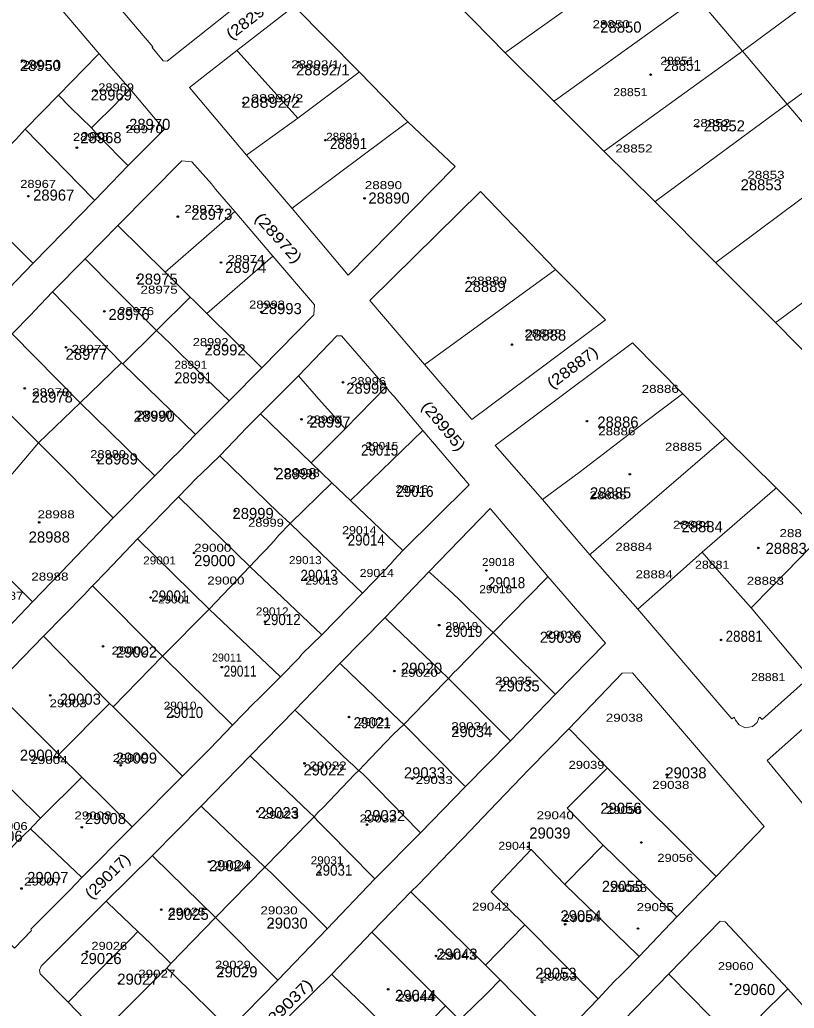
# Model space of a CAD drawing. Extents: x 650553 to 652508, y 239277 to 241647.
# Drawn here: x 650803.9 to 651055.5, y 240108.2 to 240429.4 of the extents above; entities that cross this region are included whole.
import ezdxf

# ---------------------------------------------------------------- set-up
doc = ezdxf.new("R2010")
doc.units = 0
doc.header["$PDMODE"] = 32
doc.header["$PDSIZE"] = 0.5
for name, color, linetype in [('19', 7, 'Continuous'), ('20', 7, 'Continuous'), ('6', 7, 'Continuous')]:
    doc.layers.add(name, color=color, linetype=linetype)
doc.layers.add('3', color=7, linetype='Continuous', lineweight=13)
doc.layers.add('5', color=7, linetype='Continuous', lineweight=13)

msp = doc.modelspace()

# ---------------------------------------------------------------- linework, layer by layer
at = {"layer": '3'}
for p, q in [((650859.02, 240407.32), (650874.38, 240419.42)), ((650953.54, 240373.57), (650977.886, 240348.17)), ((650956.67, 240270.53), (650975.44, 240248.44)), ((651002.97, 240217.17), (651045.69, 240167.24)), ((651000, 240104.22), (651014.69, 240119.32))]:
    msp.add_line(p, q, dxfattribs=at)
for points in [[(650832.82, 240437.45), (650847.119, 240420.59), (650846.839, 240420.337), (650850.433, 240416.034), (650851.723, 240415.899), (650884.79, 240442.24), (650880.06, 240447.42), (650879.76, 240447.15), (650863.92, 240463.81), (650845.72, 240482.71), (650830.23, 240498.54), (650814.88, 240515.1)], [(650963.52, 240488.81), (650925.94, 240459.4), (650925.48, 240455.02), (650945.81, 240434.62), (650961.6, 240418.64), (650977.42, 240402.86), (650993.66, 240386.64), (651010.27, 240370.23), (651029.97, 240350.43), (651049.39, 240330.95), (651070.65, 240309.46), (651091.16, 240289.1)], [(650779.71, 240413.95), (650806.93, 240441.68), (650809.94, 240441.52), (650829.64, 240418.33), (650839.71, 240406.79), (650850.75, 240393.72), (650839.03, 240381.99), (650828.2, 240370.72), (650808.21, 240350.23), (650794.9, 240336.56), (650781.8, 240323.07), (650768.64, 240309.58), (650755.41, 240295.93), (650741.91, 240281.85), (650728.35, 240268.09)], [(650874.38, 240419.42), (650893.01, 240433.8), (650914.15, 240412.42), (650929.978, 240396.24), (650945.306, 240381.724)], [(650945.306, 240381.724), (650910.543, 240346.406), (650892.33, 240368.07), (650877.5, 240385.33), (650859.02, 240407.32)], [(650787.85, 240313.79), (650794.22, 240320.09), (650795.45, 240321.44), (650801.38, 240327.33), (650807.43, 240333.47), (650808.64, 240334.74), (650814.48, 240340.93), (650825.07, 240351.63), (650835.69, 240362.55), (650856.48, 240383.5), (650859.73, 240383.17), (650866.12, 240376.02), (650867.47, 240374.36), (650873.78, 240367.01), (650886.12, 240352.53), (650899.62, 240336.77), (650899.4, 240333.52)], [(650935.379, 240317.358), (650917.632, 240338.107), (650953.54, 240373.57)], [(650977.886, 240348.17), (650994.115, 240331.864), (650950.714, 240299.452), (650935.379, 240317.358)], [(650899.4, 240333.52), (650882.46, 240316.3), (650871.84, 240305.54), (650860.95, 240294.62), (650855.64, 240289.08), (650853.1, 240286.62), (650847.74, 240281.16), (650834.26, 240267.54), (650817.4, 240250)], [(650831.89, 240250), (650842.09, 240260.74), (650848.02, 240266.82), (650849.46, 240268.28), (650855.46, 240274.36), (650861.39, 240280.47), (650862.83, 240281.82), (650868.89, 240287.72), (650875.8, 240294.96), (650877.19, 240296.42), (650882.1, 240301.29), (650894.43, 240313.67), (650906.83, 240326.67), (650908.39, 240326.62), (650921.14, 240311.96), (650922.6, 240310.52), (650922.89, 240310.12), (650923.87, 240308.73), (650925.52, 240306.94), (650934.86, 240295.88), (650949.85, 240278.27)], [(651002.88, 240324.42), (650958.28, 240291.03), (650973.65, 240273.43), (650989.05, 240255.53), (651004.69, 240237.82)], [(651087.57, 240239.54), (651064.69, 240262.07), (651049.64, 240277.24), (651033.12, 240293.56), (651019.23, 240307.86), (651002.88, 240324.42)], [(650949.85, 240278.27), (650928.34, 240256.94), (650925.35, 240253.81), (650924.47, 240252.7), (650921.88, 240250)], [(650810.87, 240121.85), (650831.93, 240142.92), (650846.95, 240157.77), (650862.81, 240173.82), (650878.68, 240190.23), (650893.26, 240205.07), (650907.87, 240220.21), (650922.56, 240235.11), (650936.76, 240250), (650956.67, 240270.53)], [(650725.8, 240250), (650717.68, 240241.5), (650704.33, 240227.66), (650704.28, 240225.38), (650711.26, 240218.39), (650712.71, 240217.11), (650719.74, 240210.07), (650727.37, 240202.26), (650728.66, 240201), (650749.48, 240180.42), (650768.67, 240200.35), (650774.4, 240206.01), (650775.68, 240207.3), (650781.35, 240212.99), (650786.73, 240218.51), (650788.1, 240219.97), (650794.65, 240226.67), (650800.78, 240232.68), (650801.8, 240233.71), (650808, 240240.22), (650817.4, 240250)], [(650831.89, 240250), (650827.51, 240245.39), (650826.78, 240244.72), (650824.86, 240242.62), (650811.56, 240229.04), (650794.97, 240212.04), (650781.7, 240198.63), (650756.76, 240173.01), (650770.74, 240159.15), (650772.14, 240157.81), (650772.9, 240157.17)], [(650820.08, 240146.53), (650824.01, 240150.65), (650840.42, 240167.09), (650856.74, 240183.6), (650864.2, 240191.06), (650865.62, 240192.52), (650872.93, 240200.2), (650879.96, 240207.28), (650881.3, 240208.63), (650888.53, 240215.85), (650894.49, 240221.96), (650895.64, 240223.36), (650902.04, 240229.48), (650915.18, 240243.03), (650921.88, 240250)], [(650975.44, 240248.44), (650994.17, 240226.84), (650977.88, 240210.19), (650963.32, 240195.05), (650948.63, 240180.21), (650934.05, 240165.2), (650919.2, 240150.25), (650903.76, 240134.01), (650887.65, 240117.31), (650871.97, 240101.3)], [(651004.69, 240237.82), (651035.18, 240202.17), (651035.94, 240202.81), (651036.11, 240202.584), (651036.41, 240201.81), (651037.555, 240200.241), (651039.578, 240199.34), (651041.891, 240199.7), (651043.384, 240201.007), (651044.011, 240202.539), (651044.251, 240202.72), (651045, 240202.01), (651060.45, 240215.71), (651087.57, 240239.54)], [(651046.67, 240188.64), (651067.79, 240207.42), (651095.04, 240231.27)], [(651002.97, 240217.17), (650999.6, 240217.03), (650982.26, 240199.01)], [(650982.26, 240199.01), (650969.26, 240185.78), (650956.52, 240172.47), (650947.93, 240163.4), (650943.47, 240158.84), (650933.41, 240148.36), (650930.92, 240145.99)], [(651068.91, 240161.72), (651055.65, 240177.73), (651046.67, 240188.64)], [(651045.69, 240167.24), (651030.09, 240151.02), (651017.38, 240137.84), (651005.05, 240125.03), (651000, 240119.78)], [(650818.42, 240144.86), (650819.503, 240145.95), (650820.08, 240146.53)], [(650930.92, 240145.99), (650924.769, 240139.63), (650918.26, 240132.9), (650905.2, 240119.22), (650892.49, 240106.64), (650880, 240093.44)], [(650785.53, 240144.32), (650788.76, 240141.22), (650788.44, 240140.92), (650802.1, 240127.68), (650807.72, 240133.44), (650807.48, 240133.9), (650818.42, 240144.86)], [(651014.69, 240119.32), (651031.37, 240136.47), (651033.06, 240136.27), (651053.41, 240114.49), (651063.76, 240102.95), (651079.09, 240086.95)], [(650810.87, 240121.85), (650810.26, 240120.51), (650810.53, 240119.41)], [(650871.97, 240101.3), (650850.3, 240079.24), (650829.93, 240099.47), (650819.64, 240110.18), (650810.53, 240119.41)], [(650991.82, 240111.21), (650996.99, 240116.84), (650999.05, 240118.78), (651000, 240119.78)], [(650978.95, 240097.99), (650985.03, 240104.18), (650986.07, 240105.29), (650991.82, 240111.21)]]:
    msp.add_lwpolyline(points, dxfattribs=at)
at = {"layer": '5'}
for p, q in [((651038.66, 240419.13), (651024.02, 240436.43)), ((651053.14, 240401.96), (651038.66, 240419.13)), ((650873.78, 240367.01), (650851.09, 240347.3)), ((650886.12, 240352.53), (650864.68, 240333.94)), ((651000, 240293.3), (651006.86, 240298.53)), ((650911.34, 240273.15), (650934.86, 240295.88)), ((651000, 240293.3), (650985.56, 240282.3)), ((650842.09, 240260.74), (650865.42, 240237.81)), ((651018.38, 240250), (651025.53, 240256.36)), ((651025.53, 240256.36), (651031.11, 240250)), ((650878.66, 240251.69), (650902.04, 240229.48)), ((650907.96, 240250), (650915.18, 240243.03)), ((651018.38, 240250), (651004.69, 240237.82)), ((651031.11, 240250), (651041.44, 240238.23)), ((650865.42, 240237.81), (650888.53, 240215.85)), ((650816.57, 240190.66), (650832.98, 240207.15)), ((650810.6, 240169.99), (650824.01, 240183.28)), ((650929.29, 240095.81), (650942.18, 240109.01))]:
    msp.add_line(p, q, dxfattribs=at)
for points in [[(650961.6, 240418.64), (650962.1, 240418.998), (651010.04, 240453.28)], [(651074.25, 240445.5), (651073.75, 240445.13), (651038.66, 240419.13)], [(650977.42, 240402.86), (650977.92, 240403.22), (651024.02, 240436.43)], [(651089.17, 240428.21), (651088.67, 240427.846), (651053.14, 240401.96)], [(650874.38, 240419.42), (650874.831, 240418.92), (650894.2, 240397.43)], [(650993.66, 240386.64), (650994.16, 240387.001), (651038.66, 240419.13)], [(650816.46, 240404.86), (650829.151, 240417.83), (650829.64, 240418.33)], [(650914.15, 240412.42), (650913.65, 240412.044), (650894.2, 240397.43)], [(650831.7, 240398.71), (650839.214, 240406.29), (650839.71, 240406.79)], [(650785.52, 240372.91), (650789.1, 240376.24), (650799.71, 240387.51), (650802.7, 240390.51), (650805.63, 240393.83), (650816.46, 240404.86)], [(650816.46, 240404.86), (650820.11, 240401.1), (650820.49, 240400.73), (650827.17, 240394.19), (650829.44, 240391.6), (650830.39, 240390.7)], [(651053.14, 240401.96), (651010.77, 240370.6), (651010.27, 240370.23)], [(651071.47, 240380.47), (651070.98, 240381.01), (651053.14, 240401.96)], [(650827.17, 240394.19), (650830.98, 240398.06), (650831.7, 240398.71)], [(650894.2, 240397.43), (650878, 240385.692), (650877.5, 240385.33)], [(650805.63, 240393.83), (650827.712, 240371.22), (650828.2, 240370.72)], [(650929.978, 240396.24), (650929.478, 240395.866), (650892.83, 240368.444), (650892.33, 240368.07)], [(650830.39, 240390.7), (650838.534, 240382.49), (650839.03, 240381.99)], [(651029.97, 240350.43), (651030.47, 240350.803), (651070.98, 240381.01)], [(650786.82, 240371.66), (650807.711, 240350.73), (650808.21, 240350.23)], [(651049.39, 240330.95), (651049.89, 240331.32), (651080.47, 240353.97), (651088.54, 240359.9), (651095.77, 240365.01)], [(650835.69, 240362.55), (650851.09, 240347.3), (650855.36, 240343.17), (650859.2, 240339.25), (650860.44, 240338.1), (650864.68, 240333.94), (650882.46, 240316.3)], [(650825.07, 240351.63), (650834.88, 240341.85), (650844.45, 240332.14), (650848.26, 240328.38), (650852.83, 240324.06), (650862.1, 240314.83), (650871.84, 240305.54)], [(650977.886, 240348.17), (650977.386, 240347.808), (650935.879, 240317.72), (650935.379, 240317.358)], [(650814.48, 240340.93), (650836.94, 240317.85), (650837.38, 240317.56), (650860.95, 240294.62)], [(650837.38, 240317.56), (650848.26, 240328.38), (650859.2, 240339.25)], [(650801.38, 240327.33), (650823.52, 240304.87), (650847.74, 240281.16)], [(650784.94, 240263.21), (650796.11, 240275.63), (650809.97, 240291.87), (650823.52, 240304.87), (650836.94, 240317.85)], [(650787.85, 240313.79), (650801.15, 240300.62), (650809.97, 240291.87), (650834.26, 240267.54)], [(650894.43, 240313.67), (650901.02, 240306.09), (650906.75, 240299.71), (650909.62, 240296.48)], [(650898.55, 240285.42), (650909.62, 240296.48), (650922.89, 240310.12)], [(651006.86, 240298.53), (651018.73, 240307.483), (651019.23, 240307.86)], [(650882.1, 240301.29), (650898.55, 240285.42), (650905.23, 240278.91), (650911.34, 240273.15), (650928.34, 240256.94)], [(651000, 240264.98), (651032.62, 240293.129), (651033.12, 240293.56)], [(650868.89, 240287.72), (650887.94, 240269.1), (650891.73, 240265.66), (650907.96, 240250)], [(650761.43, 240286.46), (650784.682, 240263.372), (650808, 240240.22)], [(650985.56, 240282.3), (650974.15, 240273.802), (650973.65, 240273.43)], [(650855.46, 240274.36), (650878.66, 240251.69), (650882.21, 240255.45), (650883.89, 240257.26), (650886.53, 240260.07), (650887.91, 240261.75), (650891.73, 240265.66), (650905.23, 240278.91)], [(651025.53, 240256.36), (651049.14, 240276.807), (651049.64, 240277.24)], [(651000, 240264.98), (650989.55, 240255.962), (650989.05, 240255.53)], [(651052.92, 240250), (651064.202, 240261.57), (651064.69, 240262.07)], [(650834.16, 240206.16), (650850.22, 240222.56), (650865.42, 240237.81), (650878.66, 240251.69)], [(650936.76, 240250), (650937.26, 240249.549), (650943.23, 240244.17), (650946.38, 240241.23), (650955.25, 240232.48), (650957.62, 240230.31), (650960.01, 240227.88)], [(651052.92, 240250), (651041.928, 240238.73), (651041.44, 240238.23)], [(650957.62, 240230.31), (650974.949, 240247.94), (650975.44, 240248.44)], [(650827.51, 240245.39), (650850.22, 240222.56), (650872.93, 240200.2)], [(651041.44, 240238.23), (651060.028, 240216.21), (651060.45, 240215.71)], [(650922.56, 240235.11), (650923.06, 240234.63), (650940.26, 240218.12), (650943.111, 240215.289), (650943.12, 240215.28)], [(650830.427, 240099.97), (650838.9, 240108.5), (650849.92, 240119.54), (650851.66, 240121.24), (650852.94, 240122.69), (650867.5, 240137.7), (650883.45, 240154), (650883.488, 240154.039), (650897.9, 240168.78), (650899.47, 240170.4), (650900.81, 240171.86), (650902.31, 240173.34), (650912.69, 240184.19), (650913.98, 240185.38), (650917.72, 240189.34), (650925.24, 240197.18), (650928.61, 240200.38), (650941.88, 240213.99), (650943.06, 240215.23), (650943.111, 240215.289), (650944.72, 240217.14), (650946.06, 240218.3), (650956.23, 240228.91), (650957.62, 240230.31)], [(650811.56, 240229.04), (650832.98, 240207.15), (650834.16, 240206.16), (650856.74, 240183.6)], [(650960.01, 240227.88), (650977.38, 240210.685), (650977.88, 240210.19)], [(650907.87, 240220.21), (650908.37, 240219.732), (650927.08, 240201.83), (650928.61, 240200.38)], [(650943.12, 240215.28), (650962.821, 240195.55), (650963.32, 240195.05)], [(650794.97, 240212.04), (650816.57, 240190.66), (650824.01, 240183.28), (650840.42, 240167.09)], [(650893.26, 240205.07), (650893.76, 240204.592), (650910.72, 240188.37), (650912.06, 240187.22), (650913.92, 240185.43), (650913.98, 240185.38), (650915.38, 240184.2)], [(650781.7, 240198.63), (650798.02, 240182.54), (650802.52, 240177.97), (650810.6, 240169.99), (650808.01, 240167.19), (650807.31, 240166.49), (650824.01, 240150.65)], [(650928.61, 240200.38), (650948.134, 240180.71), (650948.63, 240180.21)], [(650994.76, 240186.21), (650982.748, 240198.51), (650982.26, 240199.01)], [(650878.68, 240190.23), (650879.18, 240189.752), (650897.91, 240171.85), (650899.47, 240170.4), (650900.53, 240169.14), (650904.05, 240165.61)], [(650993.4, 240161.21), (650981.71, 240173.23), (650994.26, 240185.713), (650994.76, 240186.21)], [(651030.09, 240151.02), (651029.59, 240151.518), (650994.76, 240186.21)], [(650915.38, 240184.2), (650933.559, 240165.7), (650934.05, 240165.2)], [(650862.81, 240173.82), (650863.31, 240173.342), (650883.39, 240154.13), (650883.488, 240154.039), (650885.39, 240152.26), (650888.11, 240149.55)], [(650785.53, 240144.32), (650800.78, 240159.87), (650803.27, 240162.56), (650807.31, 240166.49)], [(650904.05, 240165.61), (650918.707, 240150.75), (650919.2, 240150.25)], [(650980.93, 240148.42), (650969.96, 240159.74), (650956.96, 240146), (650967.98, 240135.32)], [(650993.4, 240161.21), (650992.913, 240160.71), (650981.417, 240148.92), (650980.93, 240148.42)], [(651017.38, 240137.84), (651016.88, 240138.327), (650993.4, 240161.21)], [(650846.95, 240157.77), (650847.45, 240157.282), (650867.5, 240137.7)], [(650888.11, 240149.55), (650903.26, 240134.506), (650903.76, 240134.01)], [(650930.92, 240145.99), (650931.42, 240145.499), (650955.14, 240122.23), (650956.48, 240120.84), (650959.96, 240117.36)], [(651005.05, 240125.03), (651004.55, 240125.515), (650980.93, 240148.42)], [(650831.93, 240142.92), (650832.43, 240142.441), (650842.17, 240133.1), (650846.48, 240129.06), (650852.94, 240122.69)], [(650867.5, 240137.7), (650887.156, 240117.81), (650887.65, 240117.31)], [(650967.98, 240135.32), (650967.49, 240134.82), (650955.14, 240122.23)], [(650967.98, 240135.32), (650991.326, 240111.71), (650991.82, 240111.21)], [(650842.17, 240133.1), (650840.14, 240131), (650829, 240119.77)], [(650918.26, 240132.9), (650918.76, 240132.401), (650942.18, 240109.01), (650946.68, 240104.38)], [(650851.66, 240121.24), (650853.76, 240119.15), (650854.33, 240118.56)], [(650829, 240119.77), (650820.128, 240110.68), (650819.64, 240110.18)], [(650854.33, 240118.56), (650871.47, 240101.789), (650871.97, 240101.3)], [(650905.2, 240119.22), (650905.7, 240118.739), (650916.28, 240108.57), (650918.43, 240106.37), (650924.82, 240100.3), (650925.76, 240099.39), (650929.29, 240095.81)], [(650946.68, 240104.38), (650950.89, 240108.34), (650956.05, 240113.4), (650959.96, 240117.36)], [(650959.96, 240117.36), (650978.46, 240098.49), (650978.95, 240097.99)], [(651014.69, 240119.32), (651015.181, 240118.82), (651034.33, 240099.34), (651038, 240095.56)], [(651038, 240095.56), (651038.454, 240096.06), (651039.09, 240096.76), (651045.68, 240102.8), (651046.44, 240103.65), (651044.58, 240105.87), (651052.91, 240114.002), (651053.41, 240114.49)]]:
    msp.add_lwpolyline(points, dxfattribs=at)
at = {"layer": '6'}
for p in [(650993.601, 240428.07), (650804.634, 240416.095), (650894.4, 240415.615), (651008.801, 240411.535), (650828.507, 240406.26), (650876.459, 240402.375), (650838.775, 240394.39), (651024.05, 240394.68), (650903.125, 240390.245), (650822.403, 240387.79), (651041.426, 240376.195), (650806.678, 240372.03), (650915.873, 240371.323), (650855.222, 240365.4), (650869.247, 240350.475), (650842.121, 240345.465), (650949.617, 240345.464), (650831.338, 240334.595), (650882.344, 240334.415), (650818.886, 240322.9), (650865.409, 240322.395), (650963.807, 240323.811), (650805.469, 240309.6), (650854.599, 240311.5), (650908.891, 240311.575), (650842.466, 240299.505), (650895.403, 240299.545), (650988.105, 240298.925), (650917.619, 240291.635), (650829.106, 240286.205), (650886.889, 240283.475), (651002.059, 240281.695), (650931.344, 240276.41), (650873.772, 240269.705), (650810.156, 240266.045), (651018.563, 240265.69), (650910.352, 240260.97), (650860.494, 240256.085), (651043.79, 240257.735), (650955.462, 240250.42), (650896.737, 240247.57), (650846.372, 240241.65), (650883.598, 240233.77), (650940.106, 240232.644), (650975.311, 240229.315), (651031.71, 240227.85), (650830.888, 240225.775), (650869.52, 240219.005), (650925.542, 240217.745), (650960.54, 240212.68), (650813.76, 240209.85), (650853.624, 240203.08), (650910.855, 240202.795), (650945.923, 240197.749), (650896.375, 240187.735), (650836.678, 240187.12), (650931.417, 240182.79), (651014.076, 240184.095), (650881.093, 240172.134), (650824.04, 240166.965), (650916.666, 240167.815), (651005.824, 240162.025), (650969.018, 240160.62), (650865.347, 240155.76), (650901.359, 240152.205), (650804.426, 240147.085), (650849.822, 240140.23), (650885.793, 240135.674), (650981.05, 240135.475), (651004.739, 240134.075), (650825.647, 240126.55), (650939.056, 240125.185), (650869.447, 240119.5), (650836.135, 240116.285), (650923.545, 240114.355), (650973.544, 240116.655), (651034.962, 240116.015)]:
    msp.add_point(p, dxfattribs=at)

# ---------------------------------------------------------------- texts
at = {"layer": '19'}
for s, rotation, width, p in [('(28293)', 37.664, 1.15, (650872.62, 240422.724)), ('(28972)', 311.944, 1.2, (650879.936, 240364.705)), ('(28887)', 36.817, 1.15, (650976.822, 240309.29)), ('(28995)', 309.445, 1.15, (650934.107, 240303.594)), ('(29017)', 45.014, 1.1, (650827.176, 240143.381)), ('(29037)', 44.915, 1.2, (650885.223, 240101.459))]:
    msp.add_text(s, height=3.6, rotation=rotation, dxfattribs=dict(at, width=width)).set_placement(p)
for s, p in [('28850', (650992.463, 240425.172)), ('28950', (650803.876, 240412.722)), ('28892/1', (650893.61, 240411.285)), ('28969', (650826.91, 240403.145)), ('28970', (650839.388, 240393.568)), ('28852', (651026.055, 240393.088)), ('28968', (650823.551, 240389.258)), ('28853', (651038.052, 240373.933)), ('28967', (650808.195, 240370.583)), ('28890', (650917.123, 240369.625)), ('28973', (650859.543, 240364.357)), ('28974', (650870.579, 240347.117)), ('28975', (650841.788, 240343.287)), ('28889', (650948.317, 240340.893)), ('28993', (650882.098, 240333.71)), ('28976', (650832.67, 240331.795)), ('28888', (650967.991, 240325.09)), ('28992', (650863.863, 240320.302)), ('28977', (650818.753, 240318.866)), ('28996', (650909.93, 240307.852)), ('28978', (650807.716, 240304.979)), ('28990', (650840.829, 240298.753)), ('28997', (650897.934, 240296.838)), ('28886', (650991.505, 240296.837)), ('28989', (650828.832, 240284.866)), ('28998', (650886.896, 240280.078)), ('28885', (650989.105, 240273.852)), ('28999', (650872.98, 240267.148)), ('28884', (651018.856, 240262.838)), ('28988', (650806.758, 240259.487)), ('28883', (651046.148, 240255.798)), ('29000', (650860.503, 240251.825)), ('29036', (650972.798, 240226.925)), ('29002', (650835.07, 240222.135)), ('29020', (650927.687, 240216.869)), ('29035', (650959.361, 240211.123)), ('29003', (650816.835, 240206.812)), ('29034', (650944.004, 240196.278)), ('29004', (650803.879, 240188.615)), ('29009', (650835.072, 240187.658)), ('29022', (650896.017, 240183.828)), ('29033', (650928.649, 240182.87)), ('29038', (651013.587, 240182.87)), ('29056', (650992.474, 240171.377)), ('29023', (650881.141, 240169.941)), ('29032', (650915.692, 240168.983)), ('29008', (650824.993, 240168.024)), ('29006', (650791.403, 240162.278)), ('29039', (650969.391, 240163.311)), ('29024', (650865.304, 240152.702)), ('29007', (650806.279, 240148.87)), ('29055', (650992.953, 240145.998)), ('29025', (650851.868, 240136.899)), ('29054', (650979.516, 240136.42)), ('29030', (650884.02, 240134.026)), ('29043', (650939.206, 240123.97)), ('29026', (650823.557, 240122.533)), ('29029', (650867.705, 240118.224)), ('29053', (650971.359, 240117.745)), ('29027', (650835.554, 240115.829)), ('29044', (650925.77, 240110.562)), ('29060', (651035.888, 240112.47))]:
    msp.add_text(s, height=3.6, dxfattribs=at).set_placement(p)
for s, width, p in [('28851', 0.9, (651013.098, 240412.721)), ('28892/2', 1.1, (650875.854, 240400.751)), ('28891', 0.9, (650904.647, 240387.342)), ('28991', 0.9, (650854.265, 240311.204)), ('29015', 0.9, (650914.731, 240287.74)), ('29016', 0.9, (650926.249, 240274.332)), ('29014', 0.9, (650910.411, 240258.529)), ('29013', 0.9, (650895.056, 240247.036)), ('29018', 0.9, (650956, 240244.643)), ('29001', 0.9, (650846.587, 240240.332)), ('29012', 0.9, (650883.059, 240232.671)), ('29019', 0.9, (650942.084, 240228.841)), ('28881', 0.9, (651033.189, 240227.24)), ('29011', 0.8, (650870.102, 240215.91)), ('29010', 0.9, (650851.386, 240202.502)), ('29021', 0.9, (650912.332, 240199.151)), ('29031', 0.9, (650899.857, 240151.265))]:
    msp.add_text(s, height=3.6, dxfattribs=dict(at, width=width)).set_placement(p)
at = {"layer": '20'}
for s, width, p in [('28850', 1.25, (650989.951, 240426.615)), ('28950', 1.25, (650804.798, 240413.363)), ('28892/1', 1.25, (650892.037, 240413.58)), ('28851', 1.15, (651011.933, 240414.722)), ('28969', 1.2, (650829.369, 240406.084)), ('28851', 1.15, (650996.661, 240404.542)), ('28892/2', 1.35, (650878.994, 240402.562)), ('28852', 1.25, (651022.548, 240394.508)), ('28970', 1.25, (650838.283, 240392.511)), ('28968', 1.2, (650821.159, 240390.007)), ('28891', 1.1, (650903.387, 240390.04)), ('28852', 1.25, (650997.367, 240386.234)), ('28967', 1.2, (650804.027, 240374.728)), ('28853', 1.25, (651040.238, 240377.674)), ('28890', 1.25, (650915.963, 240374.332)), ('28973', 1.25, (650857.347, 240366.551)), ('28974', 1.25, (650871.308, 240350.324)), ('28889', 1.25, (650950.057, 240343.316)), ('28975', 1.25, (650843.084, 240340.347)), ('28976', 1.2, (650835.871, 240333.393)), ('28993', 1.2, (650878.382, 240335.52)), ('28992', 1.2, (650860.06, 240323.328)), ('28888', 1.25, (650967.783, 240326.145)), ('28977', 1.25, (650820.698, 240321.124)), ('28991', 1.1, (650854.109, 240315.968)), ('28996', 1.2, (650911.233, 240310.634)), ('28886', 1.25, (651005.9, 240308.128)), ('28978', 1.25, (650807.897, 240307.027)), ('28990', 1.2, (650841.866, 240299.712)), ('28997', 1.2, (650897.006, 240298.169)), ('28886', 1.25, (650991.773, 240294.343)), ('29015', 1.1, (650916.194, 240289.587)), ('28885', 1.25, (651013.456, 240289.307)), ('28989', 1.2, (650826.764, 240286.917)), ('28998', 1.2, (650889.726, 240280.773)), ('29016', 1.1, (650925.913, 240275.593)), ('28885', 1.25, (650988.935, 240273.545)), ('28988', 1.25, (650809.633, 240267.365)), ('28999', 1.2, (650878.049, 240264.635)), ('29014', 1.15, (650908.616, 240262.217)), ('28884', 1.25, (651016.086, 240263.978)), ('28883', 1.25, (651050.686, 240261.259)), ('29000', 1.25, (650860.512, 240256.505)), ('28884', 1.25, (650997.342, 240256.809)), ('29001', 1.1, (650843.954, 240252.384)), ('29013', 1.1, (650891.312, 240252.489)), ('29018', 1.1, (650954.014, 240251.866)), ('28881', 1.15, (651023.251, 240250.994)), ('28988', 1.25, (650807.605, 240247.142)), ('29014', 1.15, (650914.294, 240248.31)), ('28884', 1.25, (651003.904, 240247.877)), ('29000', 1.25, (650864.768, 240245.852)), ('29013', 1.1, (650896.671, 240245.83)), ('29018', 1.1, (650953.166, 240243.043)), ('28883', 1.25, (651040.026, 240245.772)), ('28987', 1.25, (650792.995, 240240.89)), ('29001', 1.1, (650848.765, 240239.707)), ('29012', 1.1, (650880.557, 240235.826)), ('29019', 1.1, (650942.174, 240231.077)), ('29036', 1.2, (650974.786, 240228.268)), ('29002', 1.25, (650833.697, 240223.106)), ('29020', 1.25, (650927.614, 240215.878)), ('28881', 1.15, (651041.46, 240214.485)), ('29035', 1.25, (650958.257, 240213.284)), ('29003', 1.25, (650813.528, 240205.966)), ('29010', 1.1, (650850.633, 240205.211)), ('29038', 1.25, (650994.258, 240201.275)), ('29021', 1.1, (650913.785, 240199.873)), ('29034', 1.25, (650944.045, 240198.515)), ('29004', 1.25, (650807.333, 240187.532)), ('29009', 1.2, (650834.059, 240188.179)), ('29022', 1.25, (650897.961, 240185.752)), ('29039', 1.2, (650982.188, 240185.967)), ('29033', 1.25, (650932.458, 240181.052)), ('29038', 1.25, (651009.327, 240179.453)), ('29008', 1.25, (650821.605, 240169.511)), ('29023', 1.25, (650882.446, 240169.742)), ('29040', 1.25, (650971.777, 240169.582)), ('29056', 1.2, (650994.414, 240171.307)), ('29006', 1.2, (650794.8, 240166.061)), ('29032', 1.25, (650914.235, 240168.539)), ('29041', 1.15, (650959.331, 240159.664)), ('29024', 1.25, (650867.092, 240153.248)), ('29031', 1.1, (650898.375, 240154.957)), ('29056', 1.2, (651011.016, 240155.751)), ('29007', 1.25, (650805.27, 240148.059)), ('29055', 1.25, (650995.56, 240145.974)), ('29025', 1.25, (650852.1, 240138.264)), ('29030', 1.25, (650882.048, 240138.679)), ('29042', 1.25, (650950.759, 240139.895)), ('29055', 1.25, (651004.273, 240139.732)), ('29054', 1.25, (650980.269, 240136.164)), ('29026', 1.2, (650827.139, 240127.161)), ('29029', 1.2, (650867.307, 240121.016)), ('29043', 1.25, (650940.074, 240123.941)), ('29027', 1.25, (650842.352, 240118.106)), ('29060', 1.2, (651030.658, 240120.575)), ('29053', 1.25, (650972.777, 240117.139)), ('29044', 1.25, (650926.554, 240110.293))]:
    msp.add_text(s, height=2.6, dxfattribs=dict(at, width=width)).set_placement(p)
msp.add_text('29011', height=2.6, dxfattribs=at).set_placement((650866.314, 240220.842))

doc.saveas('drawing.dxf')
